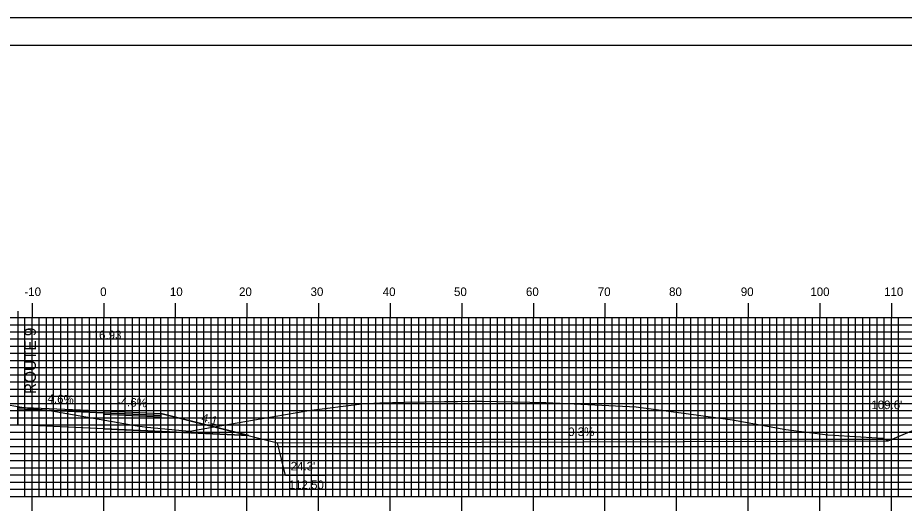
# Model space of a CAD drawing. Extents: x 1685979 to 1686323, y 461260 to 461480.
# Drawn here: x 1686133.3 to 1686257.1, y 461410.6 to 461480 of the extents above; entities that cross this region are included whole.
import ezdxf

# ---------------------------------------------------------------- set-up
doc = ezdxf.new("R2010")
doc.units = 0
for name, color, linetype in [('ANNOTATION', 7, 'Continuous'), ('BORDER', 7, 'Continuous'), ('D_Roadway_Centerline_Text', 7, 'Continuous'), ('D_Roadway_Edge_Shoulder', 7, 'Continuous'), ('D_Roadway_Edge_TW', 7, 'Continuous'), ('D_Roadway_Pavement', 7, 'Continuous'), ('D_Roadway_SlopeLines', 7, 'Continuous'), ('D_Roadway_SubGrade', 7, 'Continuous'), ('D_Text_Standard', 7, 'Continuous'), ('H_V ANNOTATION', 7, 'Continuous'), ('M_Roadway_Centerline', 7, 'Continuous'), ('MAJOR', 7, 'Continuous'), ('MINOR', 7, 'Continuous'), ('PLOT BOUNDARY', 7, 'Continuous'), ('S_Roadway_Centerline', 7, 'Continuous')]:
    doc.layers.add(name, color=color, linetype=linetype)

msp = doc.modelspace()

# ---------------------------------------------------------------- linework, layer by layer
at = {"layer": 'ANNOTATION'}
msp.add_lwpolyline([(1686176.33, 461415.98), (1686170.64, 461415.98), (1686169.51, 461420.57)], dxfattribs=at)
at = {"layer": 'BORDER'}
msp.add_lwpolyline([(1685995.66, 461266.07), (1686315.66, 461266.07), (1686315.66, 461476.07), (1685995.66, 461476.07)], close=True, dxfattribs=at)
at = {"layer": 'D_Roadway_Edge_Shoulder'}
for points in [[(1686145.26, 461425.01), (1686153.26, 461424.64), (1686153.26, 461424.39), (1686145.26, 461424.76)], [(1686145.26, 461425.01), (1686153.26, 461424.64), (1686153.26, 461424.39), (1686145.26, 461424.76)], [(1686145.26, 461425.01), (1686153.26, 461424.64), (1686153.26, 461424.39), (1686145.26, 461424.76)], [(1686145.26, 461424.76), (1686153.26, 461424.39), (1686153.26, 461424.14), (1686145.26, 461424.51)]]:
    msp.add_lwpolyline(points, close=True, dxfattribs=at)
at = {"layer": 'D_Roadway_Edge_TW'}
msp.add_lwpolyline([(1686133.26, 461425.56), (1686145.26, 461425.01), (1686145.26, 461424.76), (1686133.26, 461425.31)], close=True, dxfattribs=at)
msp.add_lwpolyline([(1686133.26, 461425.56), (1686145.26, 461425.01), (1686145.26, 461424.76), (1686133.26, 461425.31)], close=True, dxfattribs=at)
msp.add_lwpolyline([(1686133.26, 461425.56), (1686145.26, 461425.01), (1686145.26, 461424.76), (1686133.26, 461425.31)], close=True, dxfattribs=at)
for points in [[(1686133.26, 461425.56), (1686133.26, 461425.31)], [(1686145.26, 461424.76), (1686145.26, 461425.01)]]:
    msp.add_lwpolyline(points, dxfattribs=at)
at = {"layer": 'D_Roadway_Pavement'}
for points in [[(1686133.26, 461425.31), (1686133.26, 461425.06)], [(1686145.26, 461424.76), (1686145.26, 461424.51)], [(1686145.26, 461424.76), (1686145.26, 461424.51)], [(1686145.26, 461424.76), (1686145.26, 461424.51)], [(1686145.26, 461424.76), (1686145.26, 461424.51)], [(1686145.26, 461424.76), (1686145.26, 461424.51)], [(1686145.26, 461424.76), (1686145.26, 461424.51)], [(1686145.26, 461424.51), (1686145.26, 461424.76)], [(1686145.26, 461424.76), (1686145.26, 461424.51)]]:
    msp.add_lwpolyline(points, dxfattribs=at)
at = {"layer": 'D_Roadway_SlopeLines'}
for points in [[(1686153.26, 461424.64), (1686169.51, 461420.57)], [(1686153.26, 461424.64), (1686169.51, 461420.57)], [(1686153.26, 461424.64), (1686169.51, 461420.57)], [(1686153.26, 461424.64), (1686169.51, 461420.57)], [(1686169.51, 461420.57), (1686254.82, 461420.85)], [(1686169.51, 461420.57), (1686254.82, 461420.85)], [(1686169.51, 461420.57), (1686254.82, 461420.85)], [(1686169.51, 461420.57), (1686254.82, 461420.85)]]:
    msp.add_lwpolyline(points, dxfattribs=at)
at = {"layer": 'D_Roadway_SubGrade'}
msp.add_line((1686133.26, 461438.94), (1686133.26, 461423.06), dxfattribs=at)
for points in [[(1686133.26, 461425.31), (1686153.26, 461424.39), (1686153.26, 461424.64), (1686165.51, 461421.57), (1686133.26, 461423.06)], [(1686145.26, 461422.51), (1686165.51, 461421.57), (1686153.26, 461424.64), (1686153.26, 461424.39), (1686145.26, 461424.76), (1686145.26, 461424.51)], [(1686145.26, 461424.51), (1686145.26, 461424.76), (1686153.26, 461424.39), (1686153.26, 461424.64), (1686165.51, 461421.57), (1686145.26, 461422.51)], [(1686145.26, 461424.51), (1686145.26, 461424.76), (1686153.26, 461424.39), (1686153.26, 461424.64), (1686165.51, 461421.57), (1686145.26, 461422.51)], [(1686145.26, 461422.51), (1686165.51, 461421.57), (1686153.26, 461424.64), (1686153.26, 461424.39), (1686145.26, 461424.76), (1686145.26, 461424.51)]]:
    msp.add_lwpolyline(points, close=True, dxfattribs=at)
msp.add_lwpolyline([(1686133.26, 461425.06), (1686133.26, 461423.06)], dxfattribs=at)
msp.add_lwpolyline([(1686133.26, 461425.06), (1686133.26, 461423.06)], dxfattribs=at)
at = {"layer": 'MAJOR'}
for p, q in [((1686135.26, 461440.08), (1686135.26, 461438.07)), ((1686145.26, 461440.08), (1686145.26, 461438.07)), ((1686155.26, 461440.08), (1686155.26, 461438.07)), ((1686165.26, 461440.08), (1686165.26, 461438.07)), ((1686175.26, 461440.08), (1686175.26, 461438.07)), ((1686185.26, 461440.08), (1686185.26, 461438.07)), ((1686195.26, 461440.08), (1686195.26, 461438.07)), ((1686205.26, 461440.08), (1686205.26, 461438.07)), ((1686215.26, 461440.08), (1686215.26, 461438.07)), ((1686225.26, 461440.08), (1686225.26, 461438.07)), ((1686235.26, 461440.08), (1686235.26, 461438.07)), ((1686245.26, 461440.08), (1686245.26, 461438.07)), ((1686255.26, 461440.08), (1686255.26, 461438.07)), ((1686005.26, 461438.07), (1686285.26, 461438.07)), ((1686005.26, 461438.07), (1686285.26, 461438.07)), ((1686135.26, 461413.07), (1686135.26, 461438.07)), ((1686145.26, 461413.07), (1686145.26, 461438.07)), ((1686155.26, 461413.07), (1686155.26, 461438.07)), ((1686165.26, 461413.07), (1686165.26, 461438.07)), ((1686175.26, 461413.07), (1686175.26, 461438.07)), ((1686185.26, 461413.07), (1686185.26, 461438.07)), ((1686195.26, 461413.07), (1686195.26, 461438.07)), ((1686205.26, 461413.07), (1686205.26, 461438.07)), ((1686215.26, 461413.07), (1686215.26, 461438.07)), ((1686225.26, 461413.07), (1686225.26, 461438.07)), ((1686235.26, 461413.07), (1686235.26, 461438.07)), ((1686245.26, 461413.07), (1686245.26, 461438.07)), ((1686255.26, 461413.07), (1686255.26, 461438.07)), ((1686005.26, 461433.07), (1686285.26, 461433.07)), ((1686005.26, 461428.07), (1686285.26, 461428.07)), ((1686005.26, 461423.07), (1686285.26, 461423.07)), ((1686005.26, 461418.07), (1686285.26, 461418.07)), ((1686005.26, 461413.07), (1686285.26, 461413.07)), ((1686005.26, 461413.07), (1686285.26, 461413.07)), ((1686135.26, 461411.07), (1686135.26, 461413.07)), ((1686145.26, 461411.07), (1686145.26, 461413.07)), ((1686155.26, 461411.07), (1686155.26, 461413.07)), ((1686165.26, 461411.07), (1686165.26, 461413.07)), ((1686175.26, 461411.07), (1686175.26, 461413.07)), ((1686185.26, 461411.07), (1686185.26, 461413.07)), ((1686195.26, 461411.07), (1686195.26, 461413.07)), ((1686205.26, 461411.07), (1686205.26, 461413.07)), ((1686215.26, 461411.07), (1686215.26, 461413.07)), ((1686225.26, 461411.07), (1686225.26, 461413.07)), ((1686235.26, 461411.07), (1686235.26, 461413.07)), ((1686245.26, 461411.07), (1686245.26, 461413.07)), ((1686255.26, 461411.07), (1686255.26, 461413.07))]:
    msp.add_line(p, q, dxfattribs=at)
at = {"layer": 'MINOR'}
for p, q in [((1686005.26, 461437.07), (1686285.26, 461437.07)), ((1686134.26, 461413.07), (1686134.26, 461438.07)), ((1686136.26, 461413.07), (1686136.26, 461438.07)), ((1686137.26, 461413.07), (1686137.26, 461438.07)), ((1686138.26, 461413.07), (1686138.26, 461438.07)), ((1686139.26, 461413.07), (1686139.26, 461438.07)), ((1686140.26, 461413.07), (1686140.26, 461438.07)), ((1686141.26, 461413.07), (1686141.26, 461438.07)), ((1686142.26, 461413.07), (1686142.26, 461438.07)), ((1686143.26, 461413.07), (1686143.26, 461438.07)), ((1686144.26, 461413.07), (1686144.26, 461438.07)), ((1686146.26, 461413.07), (1686146.26, 461438.07)), ((1686147.26, 461413.07), (1686147.26, 461438.07)), ((1686148.26, 461413.07), (1686148.26, 461438.07)), ((1686149.26, 461413.07), (1686149.26, 461438.07)), ((1686150.26, 461413.07), (1686150.26, 461438.07)), ((1686151.26, 461413.07), (1686151.26, 461438.07)), ((1686152.26, 461413.07), (1686152.26, 461438.07)), ((1686153.26, 461413.07), (1686153.26, 461438.07)), ((1686154.26, 461413.07), (1686154.26, 461438.07)), ((1686156.26, 461413.07), (1686156.26, 461438.07)), ((1686157.26, 461413.07), (1686157.26, 461438.07)), ((1686158.26, 461413.07), (1686158.26, 461438.07)), ((1686159.26, 461413.07), (1686159.26, 461438.07)), ((1686160.26, 461413.07), (1686160.26, 461438.07)), ((1686161.26, 461413.07), (1686161.26, 461438.07)), ((1686162.26, 461413.07), (1686162.26, 461438.07)), ((1686163.26, 461413.07), (1686163.26, 461438.07)), ((1686164.26, 461413.07), (1686164.26, 461438.07)), ((1686166.26, 461413.07), (1686166.26, 461438.07)), ((1686167.26, 461413.07), (1686167.26, 461438.07)), ((1686168.26, 461413.07), (1686168.26, 461438.07)), ((1686169.26, 461413.07), (1686169.26, 461438.07)), ((1686170.26, 461413.07), (1686170.26, 461438.07)), ((1686171.26, 461413.07), (1686171.26, 461438.07)), ((1686172.26, 461413.07), (1686172.26, 461438.07)), ((1686173.26, 461413.07), (1686173.26, 461438.07)), ((1686174.26, 461413.07), (1686174.26, 461438.07)), ((1686176.26, 461413.07), (1686176.26, 461438.07)), ((1686177.26, 461413.07), (1686177.26, 461438.07)), ((1686178.26, 461413.07), (1686178.26, 461438.07)), ((1686179.26, 461413.07), (1686179.26, 461438.07)), ((1686180.26, 461413.07), (1686180.26, 461438.07)), ((1686181.26, 461413.07), (1686181.26, 461438.07)), ((1686182.26, 461413.07), (1686182.26, 461438.07)), ((1686183.26, 461413.07), (1686183.26, 461438.07)), ((1686184.26, 461413.07), (1686184.26, 461438.07)), ((1686186.26, 461413.07), (1686186.26, 461438.07)), ((1686187.26, 461413.07), (1686187.26, 461438.07)), ((1686188.26, 461413.07), (1686188.26, 461438.07)), ((1686189.26, 461413.07), (1686189.26, 461438.07)), ((1686190.26, 461413.07), (1686190.26, 461438.07)), ((1686191.26, 461413.07), (1686191.26, 461438.07)), ((1686192.26, 461413.07), (1686192.26, 461438.07)), ((1686193.26, 461413.07), (1686193.26, 461438.07)), ((1686194.26, 461413.07), (1686194.26, 461438.07)), ((1686196.26, 461413.07), (1686196.26, 461438.07)), ((1686197.26, 461413.07), (1686197.26, 461438.07)), ((1686198.26, 461413.07), (1686198.26, 461438.07)), ((1686199.26, 461413.07), (1686199.26, 461438.07)), ((1686200.26, 461413.07), (1686200.26, 461438.07)), ((1686201.26, 461413.07), (1686201.26, 461438.07)), ((1686202.26, 461413.07), (1686202.26, 461438.07)), ((1686203.26, 461413.07), (1686203.26, 461438.07)), ((1686204.26, 461413.07), (1686204.26, 461438.07)), ((1686206.26, 461413.07), (1686206.26, 461438.07)), ((1686207.26, 461413.07), (1686207.26, 461438.07)), ((1686208.26, 461413.07), (1686208.26, 461438.07)), ((1686209.26, 461413.07), (1686209.26, 461438.07)), ((1686210.26, 461413.07), (1686210.26, 461438.07)), ((1686211.26, 461413.07), (1686211.26, 461438.07)), ((1686212.26, 461413.07), (1686212.26, 461438.07)), ((1686213.26, 461413.07), (1686213.26, 461438.07)), ((1686214.26, 461413.07), (1686214.26, 461438.07)), ((1686216.26, 461413.07), (1686216.26, 461438.07)), ((1686217.26, 461413.07), (1686217.26, 461438.07)), ((1686218.26, 461413.07), (1686218.26, 461438.07)), ((1686219.26, 461413.07), (1686219.26, 461438.07)), ((1686220.26, 461413.07), (1686220.26, 461438.07)), ((1686221.26, 461413.07), (1686221.26, 461438.07)), ((1686222.26, 461413.07), (1686222.26, 461438.07)), ((1686223.26, 461413.07), (1686223.26, 461438.07)), ((1686224.26, 461413.07), (1686224.26, 461438.07)), ((1686226.26, 461413.07), (1686226.26, 461438.07)), ((1686227.26, 461413.07), (1686227.26, 461438.07)), ((1686228.26, 461413.07), (1686228.26, 461438.07)), ((1686229.26, 461413.07), (1686229.26, 461438.07)), ((1686230.26, 461413.07), (1686230.26, 461438.07)), ((1686231.26, 461413.07), (1686231.26, 461438.07)), ((1686232.26, 461413.07), (1686232.26, 461438.07)), ((1686233.26, 461413.07), (1686233.26, 461438.07)), ((1686234.26, 461413.07), (1686234.26, 461438.07)), ((1686236.26, 461413.07), (1686236.26, 461438.07)), ((1686237.26, 461413.07), (1686237.26, 461438.07)), ((1686238.26, 461413.07), (1686238.26, 461438.07)), ((1686239.26, 461413.07), (1686239.26, 461438.07)), ((1686240.26, 461413.07), (1686240.26, 461438.07)), ((1686241.26, 461413.07), (1686241.26, 461438.07)), ((1686242.26, 461413.07), (1686242.26, 461438.07)), ((1686243.26, 461413.07), (1686243.26, 461438.07)), ((1686244.26, 461413.07), (1686244.26, 461438.07)), ((1686246.26, 461413.07), (1686246.26, 461438.07)), ((1686247.26, 461413.07), (1686247.26, 461438.07)), ((1686248.26, 461413.07), (1686248.26, 461438.07)), ((1686249.26, 461413.07), (1686249.26, 461438.07)), ((1686250.26, 461413.07), (1686250.26, 461438.07)), ((1686251.26, 461413.07), (1686251.26, 461438.07)), ((1686252.26, 461413.07), (1686252.26, 461438.07)), ((1686253.26, 461413.07), (1686253.26, 461438.07)), ((1686254.26, 461413.07), (1686254.26, 461438.07)), ((1686256.26, 461413.07), (1686256.26, 461438.07)), ((1686005.26, 461436.07), (1686285.26, 461436.07)), ((1686005.26, 461435.07), (1686285.26, 461435.07)), ((1686005.26, 461434.07), (1686285.26, 461434.07)), ((1686005.26, 461432.07), (1686285.26, 461432.07)), ((1686005.26, 461431.07), (1686285.26, 461431.07)), ((1686005.26, 461430.07), (1686285.26, 461430.07)), ((1686005.26, 461429.07), (1686285.26, 461429.07)), ((1686005.26, 461427.07), (1686285.26, 461427.07)), ((1686005.26, 461426.07), (1686285.26, 461426.07)), ((1686005.26, 461425.07), (1686285.26, 461425.07)), ((1686005.26, 461424.07), (1686285.26, 461424.07)), ((1686005.26, 461422.07), (1686285.26, 461422.07)), ((1686005.26, 461421.07), (1686285.26, 461421.07)), ((1686005.26, 461420.07), (1686285.26, 461420.07)), ((1686005.26, 461419.07), (1686285.26, 461419.07)), ((1686005.26, 461417.07), (1686285.26, 461417.07)), ((1686005.26, 461416.07), (1686285.26, 461416.07)), ((1686005.26, 461415.07), (1686285.26, 461415.07)), ((1686005.26, 461414.07), (1686285.26, 461414.07))]:
    msp.add_line(p, q, dxfattribs=at)
at = {"layer": 'PLOT BOUNDARY'}
msp.add_lwpolyline([(1685979.47, 461259.95), (1686319.47, 461259.95), (1686319.47, 461479.95), (1685979.47, 461479.95)], close=True, dxfattribs=at)
at = {"layer": 'S_Roadway_Centerline'}
msp.add_lwpolyline([(1686131.08, 461425.99), (1686133.83, 461425.56), (1686137.45, 461425.11), (1686149.92, 461422.92), (1686151.33, 461422.76), (1686157.24, 461422.17), (1686157.27, 461422.17), (1686160.69, 461422.8), (1686167.39, 461423.94), (1686173.91, 461425.06), (1686181.3, 461426), (1686183.83, 461426.14), (1686187.3, 461426.23), (1686192.86, 461426.32), (1686194.65, 461426.35), (1686196.69, 461426.37), (1686197.47, 461426.39), (1686198.06, 461426.37), (1686207.02, 461426.2), (1686208.98, 461426.12), (1686218.69, 461425.64), (1686219.6, 461425.57), (1686226.21, 461424.71), (1686227.28, 461424.57), (1686233.06, 461423.77), (1686240.53, 461422.43), (1686246.36, 461421.7), (1686254.08, 461421.21), (1686254.82, 461420.85), (1686262.37, 461424.06)], dxfattribs=at)

# ---------------------------------------------------------------- texts
at = {"layer": 'ANNOTATION'}
for s, height, rotation, p in [('ROUTE 9', 1.6, 90, (1686135.79, 461427.38)), ('4.6%', 1.2, 357.3662, (1686137.4, 461426.17)), ('-4.6%', 1.2, 357.3663, (1686147.08, 461425.72)), ('4:1', 1.2, 345.9638, (1686158.84, 461423.55)), ('0.3%', 1.2, 0.1875, (1686210.12, 461421.51))]:
    msp.add_text(s, height=height, rotation=rotation, dxfattribs=at).set_placement(p)
for s, p in [("24.3' ", (1686171.37, 461416.7)), ('112.50', (1686171.1, 461414.1))]:
    msp.add_text(s, height=1.2, dxfattribs=at).set_placement(p)
at = {"layer": 'D_Roadway_Centerline_Text'}
msp.add_text('116.93', height=1.2, dxfattribs=at).set_placement((1686142.83, 461435.04))
at = {"layer": 'D_Text_Standard'}
msp.add_text("109.6'", height=1.2, dxfattribs=at).set_placement((1686252.46, 461425.27))
at = {"layer": 'H_V ANNOTATION'}
for s, p in [('-10', (1686134.19, 461441.07)), ('0', (1686144.77, 461441.07)), ('10', (1686154.51, 461441.07)), ('20', (1686164.16, 461441.07)), ('30', (1686174.15, 461441.07)), ('40', (1686184.23, 461441.07)), ('50', (1686194.18, 461441.07)), ('60', (1686204.23, 461441.07)), ('70', (1686214.26, 461441.07)), ('80', (1686224.21, 461441.07)), ('90', (1686234.23, 461441.07)), ('100', (1686243.94, 461441.07)), ('110', (1686254.24, 461441.07))]:
    msp.add_text(s, height=1.2, dxfattribs=at).set_placement(p)
at = {"layer": 'M_Roadway_Centerline'}
for s, p in [('C', (1686197.46, 461426.39)), ('L', (1686197.47, 461426.39))]:
    msp.add_text(s, height=0.0146, dxfattribs=at).set_placement(p)

doc.saveas('drawing.dxf')
